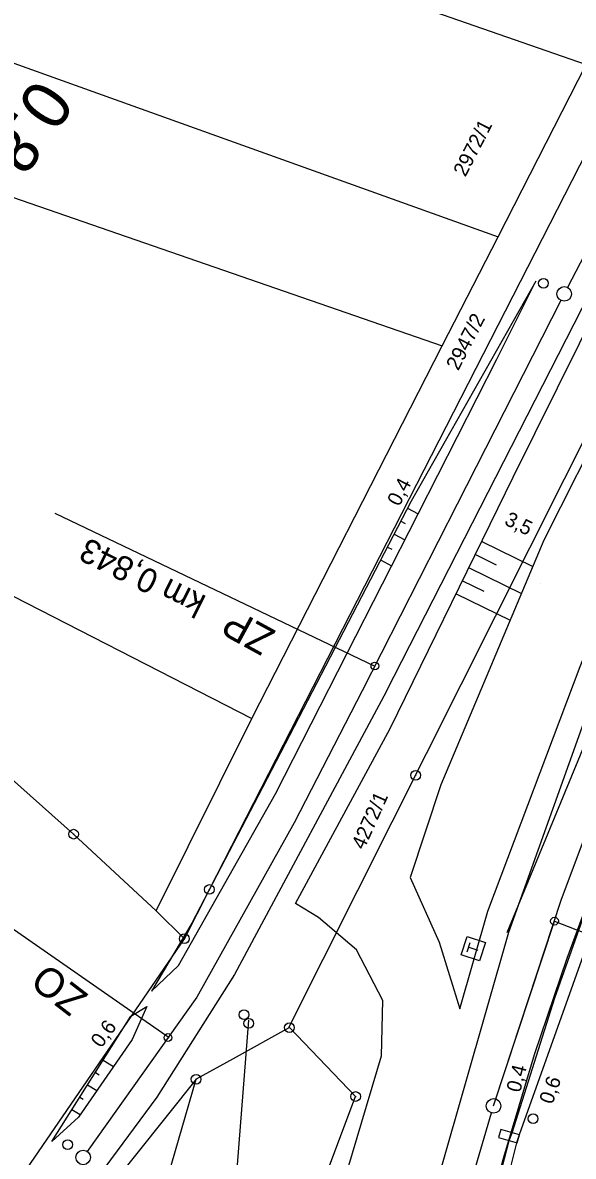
# Model space of a CAD drawing. Extents: x -658910 to -658078, y -1170373 to -1169331.
# Drawn here: x -658449.7 to -658393.1, y -1169916 to -1169799.4 of the extents above; entities that cross this region are included whole.
import ezdxf

# ---------------------------------------------------------------- set-up
doc = ezdxf.new("R2010")
doc.units = 0
for name, color, linetype in [('Vrstva 1', 7, 'Continuous'), ('Vrstva 10', 7, 'Continuous'), ('Vrstva 11', 7, 'Continuous'), ('Vrstva 14', 7, 'Continuous'), ('Vrstva 26', 7, 'Continuous'), ('Vrstva 34', 7, 'Continuous'), ('Vrstva 38', 7, 'Continuous'), ('Vrstva 39', 7, 'Continuous'), ('Vrstva 6', 7, 'Continuous'), ('Vrstva 7', 7, 'Continuous'), ('Vrstva 8', 7, 'Continuous'), ('Vrstva 9', 7, 'Continuous')]:
    doc.layers.add(name, color=color, linetype=linetype)

msp = doc.modelspace()

# ---------------------------------------------------------------- linework, layer by layer
at = {"layer": 'Vrstva 1'}
for p, q in [((-658430.581, -1169888.559), (-658430.481, -1169888.559)), ((-658433.152, -1169893.621), (-658433.052, -1169893.621)), ((-658422.339, -1169902.77), (-658422.239, -1169902.77)), ((-658431.941, -1169908.08), (-658431.841, -1169908.08)), ((-658415.53, -1169909.85), (-658415.43, -1169909.85))]:
    msp.add_line(p, q, dxfattribs=at)
for points in [[(-658535.25, -1169975.531), (-658525.109, -1169972.281), (-658506.949, -1169964.32), (-658490.84, -1169955.289), (-658479.949, -1169947.32), (-658468.961, -1169938.809), (-658451.859, -1169920.99), (-658433.102, -1169893.621), (-658430.531, -1169888.559), (-658387.09, -1169803.74)], [(-658434.91, -1170000.301), (-658433.32, -1169974.6), (-658432.57, -1169965.9), (-658431.148, -1169951.469), (-658415.48, -1169909.85), (-658422.289, -1169902.77), (-658428.09, -1169905.961)], [(-658428.09, -1169905.961), (-658431.891, -1169908.08), (-658444.09, -1169923.359), (-658456.738, -1169938.969), (-658471.32, -1169950.961), (-658489.809, -1169963.961), (-658501.559, -1169972.781), (-658503.262, -1169973.871), (-658537.41, -1169985.039)]]:
    msp.add_lwpolyline(points, dxfattribs=at)
for centre in [(-658430.531, -1169888.559), (-658433.102, -1169893.621), (-658422.289, -1169902.77), (-658431.891, -1169908.08), (-658415.48, -1169909.85)]:
    msp.add_circle(centre, 0.499, dxfattribs=at)
at = {"layer": 'Vrstva 10'}
for p, q in [((-658396.489, -1169857.081), (-658396.489, -1169857.081)), ((-658398.647, -1169912.601), (-658398.647, -1169912.601))]:
    msp.add_line(p, q, dxfattribs=at)
for points in [[(-658412.34, -1169868.25), (-658390.58, -1169825.61), (-658346.68, -1169740.23), (-658319.39, -1169686.96), (-658299.95, -1169648.82), (-658273.229, -1169598.35)], [(-658427.5, -1169951.109), (-658426.838, -1169944.052), (-658418.293, -1169924.085), (-658412.835, -1169905.664), (-658412.681, -1169899.985), (-658415.385, -1169894.759), (-658419.286, -1169891.437), (-658421.684, -1169889.994), (-658411.914, -1169872.007), (-658399.264, -1169846.174), (-658387.883, -1169823.23), (-658375.867, -1169800)], [(-658362.5, -1169799.992), (-658377.058, -1169834.921), (-658390.526, -1169867.22), (-658399.748, -1169892.989), (-658408.868, -1169924.83), (-658414.693, -1169947.06)], [(-658370.274, -1169800), (-658382.467, -1169825.639), (-658396.121, -1169852.622), (-658406.724, -1169877.812), (-658409.871, -1169887.316), (-658406.874, -1169893.983), (-658404.766, -1169900.848), (-658401.886, -1169890.78), (-658392.378, -1169865.645), (-658379.571, -1169833.72), (-658365.283, -1169800)], [(-658405.482, -1169935.482), (-658403.028, -1169926.019), (-658400.233, -1169916.097), (-658397.067, -1169905.522), (-658393.729, -1169895.606), (-658386.751, -1169876.773), (-658379.972, -1169859.803), (-658372.303, -1169841.365), (-658363.947, -1169821.339), (-658354.813, -1169800)], [(-658399.903, -1169892.997), (-658389.914, -1169868.81), (-658375.827, -1169834.718), (-658360.929, -1169800)], [(-658399.39, -1169913.576), (-658395.005, -1169899.698), (-658389.047, -1169882.978), (-658382.022, -1169865.114), (-658371.363, -1169838.762), (-658362.563, -1169817.838), (-658354.775, -1169800)], [(-658353.23, -1169800), (-658360.347, -1169815.55), (-658370.211, -1169839.636), (-658380.871, -1169865.378), (-658387.629, -1169882.876), (-658398.665, -1169913.79)], [(-658410.142, -1169849.352), (-658409.055, -1169849.917)], [(-658410.833, -1169850.683), (-658410.394, -1169850.911)], [(-658411.525, -1169852.014), (-658410.417, -1169852.59)], [(-658412.216, -1169853.345), (-658411.769, -1169853.578)], [(-658402.499, -1169852.78), (-658397.266, -1169855.342)], [(-658412.908, -1169854.676), (-658411.778, -1169855.263)], [(-658403.158, -1169854.127), (-658401.034, -1169855.167)], [(-658403.818, -1169855.474), (-658398.432, -1169858.112)], [(-658404.478, -1169856.821), (-658402.292, -1169857.891)], [(-658405.137, -1169858.168), (-658399.598, -1169860.881)], [(-658412.34, -1169868.25), (-658427.96, -1169897.31), (-658435.92, -1169909.92), (-658444.78, -1169921.89), (-658465.67, -1169943.73), (-658479.49, -1169955.1), (-658517.4, -1169976.07), (-658535.91, -1169983.41)], [(-658441.452, -1169906.108), (-658440.404, -1169906.772)], [(-658442.255, -1169907.375), (-658441.855, -1169907.628)], [(-658443.058, -1169908.643), (-658442.108, -1169909.244)], [(-658443.86, -1169909.909), (-658443.5, -1169910.137)], [(-658444.663, -1169911.176), (-658443.813, -1169911.715)], [(-658399.692, -1169914.385), (-658399.39, -1169913.576)], [(-658398.665, -1169913.79), (-658398.928, -1169914.611)], [(-658407.59, -1169944.829), (-658399.692, -1169914.385)], [(-658398.928, -1169914.611), (-658403.084, -1169931.189), (-658406.227, -1169944.399)]]:
    msp.add_lwpolyline(points, dxfattribs=at)
for points in [[(-658396.948, -1169826.018), (-658409.757, -1169848.611), (-658425.063, -1169878.073), (-658432.349, -1169892.02), (-658436.481, -1169899.019), (-658433.7, -1169896.37), (-658423.728, -1169878.729), (-658409.055, -1169849.917), (-658400.945, -1169834.015)], [(-658446.75, -1169914.47), (-658438.591, -1169901.593), (-658436.957, -1169900.606), (-658438.478, -1169903.98), (-658443.98, -1169911.957)], [(-658400.533, -1169913.239), (-658400.777, -1169914.065), (-658398.866, -1169914.629), (-658398.623, -1169913.802)]]:
    msp.add_lwpolyline(points, close=True, dxfattribs=at)
at = {"layer": 'Vrstva 14'}
for centre in [(-658396.162, -1169826.225), (-658397.225, -1169912.138), (-658445.114, -1169914.797)]:
    msp.add_circle(centre, 0.5, dxfattribs=at)
at = {"layer": 'Vrstva 26'}
msp.add_line((-658426.51, -1169902.01), (-658430.35, -1169951.67), dxfattribs=at)
for centre in [(-658426.977, -1169901.444), (-658426.472, -1169902.326)]:
    msp.add_circle(centre, 0.5, dxfattribs=at)
at = {"layer": 'Vrstva 34'}
for p, q in [((-658404.006, -1169894.959), (-658403.695, -1169894.009)), ((-658403.851, -1169894.484), (-658402.9, -1169894.795))]:
    msp.add_line(p, q, dxfattribs=at)
msp.add_lwpolyline([(-658404.637, -1169895.279), (-658404.015, -1169893.378), (-658402.114, -1169894), (-658402.736, -1169895.901), (-658404.637, -1169895.279)], dxfattribs=at)
at = {"layer": 'Vrstva 38'}
for points in [[(-658446.431, -1169849.868), (-658413.502, -1169865.579)], [(-658463.556, -1169883.682), (-658434.656, -1169903.798)], [(-658395.024, -1169891.817), (-658392.843, -1169892.686), (-658350.108, -1169908.755)]]:
    msp.add_lwpolyline(points, dxfattribs=at)
for centre in [(-658413.5, -1169865.576), (-658395.024, -1169891.817), (-658434.79, -1169903.784)]:
    msp.add_circle(centre, 0.4, dxfattribs=at)
at = {"layer": 'Vrstva 39'}
msp.add_line((-658401.291, -1169910.81), (-658395.024, -1169891.817), dxfattribs=at)
at = {"layer": 'Vrstva 6'}
for points in [[(-658380.039, -1169800), (-658391.086, -1169821.655), (-658393.686, -1169826.667)], [(-658394.367, -1169827.994), (-658405.026, -1169848.943), (-658414.801, -1169868.143), (-658421.79, -1169881.716), (-658431.813, -1169899.623), (-658443.085, -1169915.517)], [(-658394.353, -1169889.651), (-658388.744, -1169874.733), (-658378.733, -1169850.005), (-658370.721, -1169831.006)], [(-658401.06, -1169910.103), (-658394.353, -1169889.651)], [(-658410.527, -1169945.755), (-658403.539, -1169918.406), (-658401.506, -1169911.538)]]:
    msp.add_lwpolyline(points, dxfattribs=at)
for centre in [(-658394.021, -1169827.314), (-658401.291, -1169910.81), (-658443.512, -1169916.12)]:
    msp.add_circle(centre, 0.75, dxfattribs=at)
at = {"layer": 'Vrstva 8'}
for p, q in [((-658422.339, -1169902.77), (-658366.591, -1169791.74)), ((-658409.348, -1169876.818), (-658409.248, -1169876.818)), ((-658444.55, -1169882.871), (-658444.45, -1169882.871))]:
    msp.add_line(p, q, dxfattribs=at)
for points in [[(-658436, -1169890.75), (-658426.172, -1169870.98), (-658406.578, -1169832.641), (-658400.809, -1169821.461), (-658391.77, -1169803.73), (-658382.809, -1169785.65), (-658474.191, -1169749.121)], [(-658485.32, -1169771.23), (-658391.77, -1169803.73)], [(-658493.719, -1169788.129), (-658400.809, -1169821.461)], [(-658499.488, -1169800.551), (-658406.578, -1169832.641)], [(-658512.078, -1169826.949), (-658426.172, -1169870.98)], [(-658500.078, -1169839.199), (-658466.219, -1169863.551), (-658444.5, -1169882.871), (-658436, -1169890.75), (-658433.102, -1169893.621)], [(-658444.09, -1169923.359), (-658436.59, -1169924.27), (-658431.891, -1169908.08)]]:
    msp.add_lwpolyline(points, dxfattribs=at)
for centre in [(-658409.298, -1169876.818), (-658444.5, -1169882.871)]:
    msp.add_circle(centre, 0.499, dxfattribs=at)

# ---------------------------------------------------------------- texts
at = {"layer": 'Vrstva 11'}
for s, rotation, p in [('0,4', 62.54757, (-658410.993, -1169849.242)), ('3,5', 333.91039, (-658400.274, -1169850.984)), ('4272/1', 65.85759, (-658414.613, -1169884.555)), ('0,6', 54.01655, (-658441.642, -1169904.936)), ('0,4', 75.48387, (-658398.558, -1169909.51)), ('0,6', 70.64832, (-658395.237, -1169910.729))]:
    msp.add_text(s, height=1.5, rotation=rotation, dxfattribs=at).set_placement(p)
at = {"layer": 'Vrstva 39'}
for s, height, rotation, p in [('km 0,843', 2.5, 153.50449, (-658430.723, -1169858.463)), ('ZP', 3, 151.32314, (-658423.58, -1169862.014)), ('ZO', 3, 142.43586, (-658442.877, -1169899.412))]:
    msp.add_text(s, height=height, rotation=rotation, dxfattribs=at).set_placement(p)
at = {"layer": 'Vrstva 7'}
msp.add_text('0,8', height=4.999, rotation=235.28281, dxfattribs=at).set_placement((-658448.356, -1169804.937))
at = {"layer": 'Vrstva 9'}
for s, rotation, p in [('2972/1', 62.69121, (-658404.191, -1169815.354)), ('2947/2', 62.88093, (-658404.925, -1169835.287))]:
    msp.add_text(s, height=1.5, rotation=rotation, dxfattribs=at).set_placement(p)

doc.saveas('drawing.dxf')
